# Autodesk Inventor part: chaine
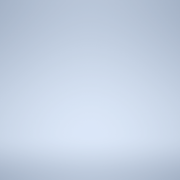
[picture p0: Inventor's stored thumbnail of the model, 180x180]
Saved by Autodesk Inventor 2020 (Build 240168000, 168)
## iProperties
Created: 2020-09
Part Number: chaine
Material: Générique
Document SubType Name: Modeling
Designer: Bruno
Density: 1 g/cm^3
Appearance: Par défaut
Author: Bruno
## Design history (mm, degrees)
node "Plan de construction1"
sketch "Esquisse1"
  geometry: L1 (-2.38, -11.558)-(-2.38, -8.886) reference; L2 (-2.38, -8.886)-(2.38, -8.886) reference; L3 (2.38, -8.886)-(2.38, -11.558) reference; L4 (1.619, 16.753)-(1.847, 15.828) reference; L5 (-1.847, 15.828)-(-1.619, 16.753) reference; L6 (-11.317, 15.043)-(-10.787, 14.252) reference; L7 (-14.258, 12.989)-(-14.361, 13.935) reference; L8 (-22.889, 9.011)-(-22.12, 8.449) reference; L9 (-24.95, 6.075)-(-25.37, 6.93) reference; L10 (-31.7, -0.614)-(-30.785, -0.879) reference; L11 (-32.632, -4.078)-(-33.319, -3.419) reference; L12 (-36.687, -12.672)-(-35.737, -12.609) reference; L13 (-36.378, -16.246)-(-37.249, -15.862) reference; L14 (-37.249, -25.709)-(-36.378, -25.325) reference; L15 (-35.737, -28.962)-(-36.687, -28.899) reference; L16 (-33.319, -38.152)-(-32.632, -37.493) reference; L17 (-30.785, -40.692)-(-31.7, -40.957) reference; L18 (-25.37, -48.501)-(-24.95, -47.646) reference; L19 (-22.12, -50.021)-(-22.889, -50.583) reference; L20 (-14.361, -55.506)-(-14.258, -54.56) reference; L21 (-10.787, -55.823)-(-11.317, -56.614) reference; L22 (-1.619, -58.324)-(-1.847, -57.4) reference; L23 (1.847, -57.4)-(1.619, -58.324) reference; L24 (11.317, -56.614)-(10.787, -55.823) reference; L25 (14.258, -54.56)-(14.361, -55.506) reference; L26 (22.889, -50.583)-(22.12, -50.021) reference; L27 (24.95, -47.646)-(25.37, -48.501) reference; L28 (31.7, -40.957)-(30.785, -40.692) reference; L29 (32.632, -37.493)-(33.319, -38.152) reference; L30 (36.687, -28.899)-(35.737, -28.962) reference; L31 (36.378, -25.325)-(37.249, -25.709) reference; L32 (37.249, -15.862)-(36.378, -16.246) reference; L33 (35.737, -12.609)-(36.687, -12.672) reference; L34 (33.319, -3.419)-(32.632, -4.078) reference; L35 (30.785, -0.879)-(31.7, -0.614) reference; L36 (25.37, 6.93)-(24.95, 6.075) reference; L37 (22.12, 8.449)-(22.889, 9.011) reference; L38 (14.361, 13.935)-(14.258, 12.989) reference; L39 (10.787, 14.252)-(11.317, 15.043) reference; L40 (242.896, 852.703)-(242.105, 852.173) reference; L41 (240.842, 855.644)-(241.788, 855.747) reference; L42 (236.865, 864.275)-(236.303, 863.506) reference; L43 (233.928, 866.336)-(234.783, 866.756) reference; L44 (227.239, 873.086)-(226.974, 872.171) reference; L45 (223.775, 874.018)-(224.434, 874.705) reference; L46 (215.181, 878.073)-(215.244, 877.123) reference; L47 (211.607, 877.764)-(211.991, 878.635) reference; L48 (202.144, 878.635)-(202.529, 877.764) reference; L49 (198.891, 877.123)-(198.954, 878.073) reference; L50 (189.701, 874.705)-(190.36, 874.018) reference; L51 (187.161, 872.171)-(186.896, 873.086) reference; L52 (179.352, 866.756)-(180.207, 866.336) reference; L53 (177.833, 863.506)-(177.271, 864.275) reference; L54 (172.347, 855.747)-(173.293, 855.644) reference; L55 (172.03, 852.173)-(171.239, 852.703) reference; L56 (169.529, 843.005)-(170.454, 843.233) reference; L57 (170.454, 839.539)-(169.529, 839.767) reference; L58 (171.239, 830.069)-(172.03, 830.599) reference; L59 (173.293, 827.128)-(172.347, 827.025) reference; L60 (177.271, 818.497)-(177.833, 819.266) reference; L61 (180.207, 816.436)-(179.352, 816.016) reference; L62 (186.896, 809.686)-(187.161, 810.601) reference; L63 (190.36, 808.754)-(189.701, 808.067) reference; L64 (198.954, 804.699)-(198.891, 805.649) reference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; C1 r 30 at (207.068, 841.386) reference; A1 r 9.53 centre (0, -20.786) between (-2.38, -11.558) and (2.38, -11.558) reference; A2 r 4.009 centre (-28.013, 2.72) between (-28.129, -1.287) and (-24.087, 3.531) reference; A3 r 9.53 centre (0, -20.786) between (-2.38, -11.558) and (2.38, -11.558) reference; A4 r 4.009 centre (6.35, 15.227) between (2.821, 13.324) and (9.015, 12.232) reference; A5 r 10.377 centre (11.923, 18.308) between (1.847, 15.828) and (2.821, 13.324) reference; A6 r 6.562 centre (-4.763, 15.227) between (1.619, 16.753) and (0.583, 19.033) reference; A7 r 39.823 centre (0, -20.786) between (0.583, 19.033) and (-0.583, 19.033) reference; A8 r 6.562 centre (4.763, 15.227) between (-0.583, 19.033) and (-1.619, 16.753) reference; A9 r 10.377 centre (-11.923, 18.308) between (-2.821, 13.324) and (-1.847, 15.828) reference; A10 r 4.009 centre (-6.35, 15.227) between (-9.015, 12.232) and (-2.821, 13.324) reference; A11 r 10.377 centre (-2.167, 20.029) between (-10.787, 14.252) and (-9.015, 12.232) reference; A12 r 6.562 centre (-16.792, 11.426) between (-11.317, 15.043) and (-13.071, 16.831) reference; A13 r 39.823 centre (0, -20.786) between (-13.071, 16.831) and (-14.166, 16.432) reference; A14 r 6.562 centre (-7.842, 14.684) between (-14.166, 16.432) and (-14.361, 13.935) reference; A15 r 10.377 centre (-24.575, 11.873) between (-14.318, 10.302) and (-14.258, 12.989) reference; A16 r 4.009 centre (-18.284, 10.883) between (-19.764, 7.158) and (-14.318, 10.302) reference; A17 r 10.377 centre (-15.996, 16.826) between (-22.12, 8.449) and (-19.764, 7.158) reference; A18 r 6.562 centre (-26.797, 3.74) between (-22.889, 9.011) and (-25.148, 10.092) reference; A19 r 39.823 centre (0, -20.786) between (-25.148, 10.092) and (-26.041, 9.342) reference; A20 r 6.562 centre (-19.5, 9.863) between (-26.041, 9.342) and (-25.37, 6.93) reference; A21 r 10.377 centre (-34.263, 1.498) between (-24.087, 3.531) and (-24.95, 6.075) reference; A22 r 4.009 centre (-28.013, 2.72) between (-28.129, -1.287) and (-24.087, 3.531) reference; A23 r 10.377 centre (-27.895, 9.087) between (-30.785, -0.879) and (-28.129, -1.287) reference; A24 r 6.562 centre (-33.569, -6.904) between (-31.7, -0.614) and (-34.192, -0.372) reference; A25 r 39.823 centre (0, -20.786) between (-34.192, -0.372) and (-34.775, -1.381) reference; A26 r 6.562 centre (-28.807, 1.345) between (-34.775, -1.381) and (-33.319, -3.419) reference; A27 r 10.377 centre (-39.818, -11.564) between (-30.951, -6.174) and (-32.632, -4.078) reference; A28 r 4.009 centre (-34.363, -8.279) between (-33.102, -12.084) and (-30.951, -6.174) reference; A29 r 10.377 centre (-36.43, -2.255) between (-35.737, -12.609) and (-33.102, -12.084) reference; A30 r 6.562 centre (-36.293, -19.222) between (-36.687, -12.672) and (-39.112, -13.297) reference; A31 r 39.823 centre (0, -20.786) between (-39.112, -13.297) and (-39.315, -14.445) reference; A32 r 6.562 centre (-34.639, -9.842) between (-39.315, -14.445) and (-37.249, -15.862) reference; A33 r 10.377 centre (-40.57, -25.739) between (-34.082, -17.641) and (-36.378, -16.246) reference; A34 r 4.009 centre (-36.568, -20.786) between (-34.082, -23.93) and (-34.082, -17.641) reference; A35 r 10.377 centre (-40.57, -15.832) between (-36.378, -25.325) and (-34.082, -23.93) reference; A36 r 6.562 centre (-34.639, -31.729) between (-37.249, -25.709) and (-39.315, -27.126) reference; A37 r 39.823 centre (0, -20.786) between (-39.315, -27.126) and (-39.112, -28.274) reference; A38 r 6.562 centre (-36.293, -22.349) between (-39.112, -28.274) and (-36.687, -28.899) reference; A39 r 10.377 centre (-36.43, -39.316) between (-33.102, -29.487) and (-35.737, -28.962) reference; A40 r 4.009 centre (-34.363, -33.293) between (-30.951, -35.397) and (-33.102, -29.487) reference; A41 r 10.377 centre (-39.818, -30.007) between (-32.632, -37.493) and (-30.951, -35.397) reference; A42 r 6.562 centre (-28.807, -42.916) between (-33.319, -38.152) and (-34.775, -40.19) reference; A43 r 39.823 centre (0, -20.786) between (-34.775, -40.19) and (-34.192, -41.2) reference; A44 r 6.562 centre (-33.569, -34.667) between (-34.192, -41.2) and (-31.7, -40.957) reference; A45 r 10.377 centre (-27.895, -50.658) between (-28.129, -40.284) and (-30.785, -40.692) reference; A46 r 4.009 centre (-28.013, -44.291) between (-24.087, -45.102) and (-28.129, -40.284) reference; A47 r 10.377 centre (-34.263, -43.069) between (-24.95, -47.646) and (-24.087, -45.102) reference; A48 r 6.562 centre (-19.5, -51.434) between (-25.37, -48.501) and (-26.041, -50.914) reference; A49 r 39.823 centre (0, -20.786) between (-26.041, -50.914) and (-25.148, -51.663) reference; A50 r 6.562 centre (-26.797, -45.312) between (-25.148, -51.663) and (-22.889, -50.583) reference; A51 r 10.377 centre (-15.996, -58.397) between (-19.764, -48.729) and (-22.12, -50.021) reference; A52 r 4.009 centre (-18.284, -52.455) between (-14.318, -51.874) and (-19.764, -48.729) reference; A53 r 10.377 centre (-24.575, -53.444) between (-14.258, -54.56) and (-14.318, -51.874) reference; A54 r 6.562 centre (-7.842, -56.255) between (-14.361, -55.506) and (-14.166, -58.003) reference; A55 r 39.823 centre (0, -20.786) between (-14.166, -58.003) and (-13.071, -58.402) reference; A56 r 6.562 centre (-16.792, -52.998) between (-13.071, -58.402) and (-11.317, -56.614) reference; A57 r 10.377 centre (-2.167, -61.6) between (-9.015, -53.804) and (-10.787, -55.823) reference; A58 r 4.009 centre (-6.35, -56.798) between (-2.821, -54.896) and (-9.015, -53.804) reference; A59 r 10.377 centre (-11.923, -59.879) between (-1.847, -57.4) and (-2.821, -54.896) reference; A60 r 6.562 centre (4.763, -56.798) between (-1.619, -58.324) and (-0.583, -60.604) reference; A61 r 39.823 centre (0, -20.786) between (-0.583, -60.604) and (0.583, -60.604) reference; A62 r 6.562 centre (-4.763, -56.798) between (0.583, -60.604) and (1.619, -58.324) reference; A63 r 10.377 centre (11.923, -59.879) between (2.821, -54.896) and (1.847, -57.4) reference; A64 r 4.009 centre (6.35, -56.798) between (9.015, -53.804) and (2.821, -54.896) reference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; 4 further points
  constraints: 82 point on circle, 20 centre point, 8 end point, 5 point on line, 5 tangent, 4 coincident
extrude "Extrusion1" new body sketch "Esquisse1" distance "d0" = 10; taper "d1" = 0 deg
sketch "Esquisse2"
  geometry: L1 (-1.651, 865.775)-(-7.953, 865.775); L2 (-7.953, 865.775)-(-7.953, 875.04); L3 (-7.953, 875.04)-(-1.651, 875.04); L4 (-1.651, 875.04)-(-1.651, 865.775); 1 further point
  constraints: 8 end point, 2 parallel, 1 horizontal, 1 perpendicular
extrude "Extrusion2" cut sketch "Esquisse2" distance "d2" = 80; taper "d3" = 0 deg
node "Solide1"
pattern_linear "Réseau rectangulaire1" dims "d6" = 15
node "Référence1"
node "Référence2"
node "Référence3"
node "Référence4"
